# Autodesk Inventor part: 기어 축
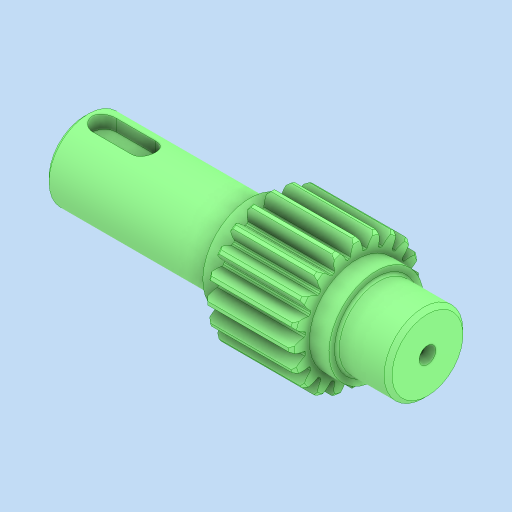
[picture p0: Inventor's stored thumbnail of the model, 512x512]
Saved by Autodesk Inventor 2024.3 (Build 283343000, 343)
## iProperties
Created: 2025-11
Part Number: 기어 축
Material: 강철, 합금
Document SubType Name: Modeling
Designer: PC2-03
Density: 7.73 g/cm^3
Appearance: 기본값
Author: jhkim
Sending System: Autodesk Inventor 2026
Preprocessor: ST-DEVELOPER v20.1
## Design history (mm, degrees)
feature "솔리드1"
node "솔리드2"
